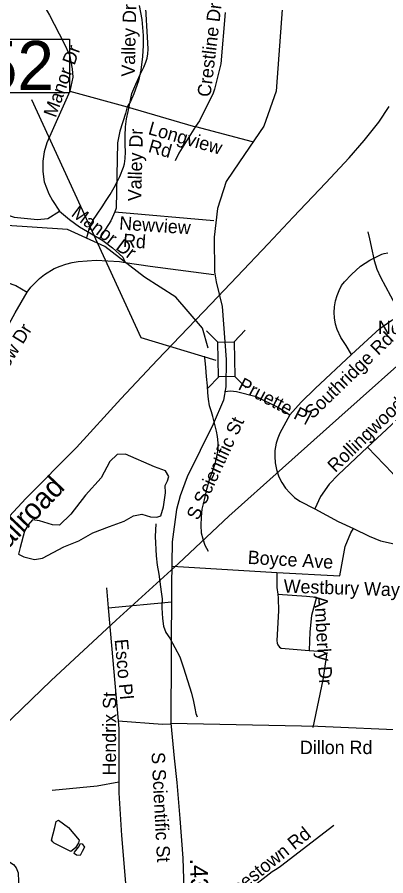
# Model space of a CAD drawing. Extents: x 1662474 to 1856135, y 779280 to 917889.
# Drawn here: x 1716545 to 1719166, y 808410 to 814512 of the extents above; entities that cross this region are included whole.
import ezdxf

# ---------------------------------------------------------------- set-up
doc = ezdxf.new("R2010")
doc.units = 0
for name, color, linetype in [('Exist Hydrographic Misc Water Feature', 7, 'Continuous'), ('Exist Hydrographic Pond Under 1500 Sq Ft', 7, 'Continuous'), ('Exist Railroad Mainline', 7, 'Continuous'), ('Exist Railroad Mainline Label', 7, 'Continuous'), ('Exist Road Non-System Type 51', 7, 'Continuous'), ('Exist Road Non-System Type 51 Label', 7, 'Continuous'), ('Exist Road Secondary Mileage Tenths English Label', 7, 'Continuous'), ('Exist Road Secondary Structure Standard Bridge CELL', 7, 'Continuous'), ('Exist Road Secondary Structure Standard Bridge Number Label', 7, 'Continuous'), ('Exist Road Secondary Type 51 Attributed', 7, 'Continuous'), ('Exist Road Secondary Type 51 Label', 7, 'Continuous'), ('Exist Utilities Electrical Transmission Line', 7, 'Continuous')]:
    doc.layers.add(name, color=color, linetype=linetype)

msp = doc.modelspace()

# ---------------------------------------------------------------- linework, layer by layer
at = {"layer": 'Exist Hydrographic Misc Water Feature'}
for points in [[(1717039.4, 812947.6), (1717062.1, 813021.5), (1717082.6, 813067.2), (1717112.9, 813113), (1717149.4, 813164.6), (1717177.9, 813208.4), (1717206.3, 813252.1), (1717234.8, 813301.9), (1717257.2, 813341.7), (1717275.5, 813379.5), (1717300.2, 813445.3), (1717308.4, 813469.2), (1717312.8, 813507.2), (1717315.2, 813555.2), (1717313.7, 813605.2), (1717312.3, 813669.3), (1717314.9, 813733.3), (1717323.4, 813789.2), (1717334, 813841.2), (1717361.2, 813968.9), (1717387.8, 814036.7), (1717422.5, 814110.3), (1717444.9, 814158.2), (1717459.3, 814192.1), (1717469.6, 814220), (1717473.8, 814251.9), (1717476.2, 814283.9), (1717474.7, 814330), (1717457.3, 814614.2)], [(1717903.3, 812159.8), (1717862.3, 812301.8), (1717673.3, 812522.3), (1717449.3, 812664.7), (1717167.4, 812883.8), (1716902.3, 813004.1), (1716435.3, 813033.3)], [(1719038.4, 812986.8), (1719049.8, 812936.6), (1719069.1, 812848.3), (1719082.4, 812784.2), (1719101.8, 812722), (1719127.3, 812663.7), (1719235.5, 812466.6)], [(1717904.5, 810714.7), (1717882.9, 810756.9), (1717867.3, 810803.1), (1717855.7, 810845.2), (1717852.3, 810901.3), (1717854.8, 810959.3), (1717861.4, 811015.2), (1717876, 811083.2), (1717892.7, 811159), (1717915.4, 811232.8), (1717935.9, 811290.6), (1717954.5, 811348.4), (1717967.1, 811402.4), (1717973.4, 811444.4), (1717973.9, 811488.3), (1717970.3, 811532.4), (1717962.6, 811570.5), (1717943.3, 811646.6), (1717935.7, 811674.8), (1717925.9, 811706.8), (1717912.3, 811751), (1717904.8, 811797.1), (1717901.2, 811843.1), (1717897.6, 811893.2), (1717892.3, 811959.2), (1717887, 812023.4), (1717881.3, 812073.4), (1717877.7, 812103.4)], [(1717530.3, 810912.3), (1717525.4, 810822.4), (1717534.2, 810684.2), (1717541.6, 810618.1), (1717553, 810554), (1717569.7, 810427.8), (1717575.3, 810379.7), (1717574.7, 810315.7), (1717578, 810239.7), (1717585.5, 810183.6), (1717602.9, 810139.4), (1717630.7, 810099.1), (1717701.4, 809966.4), (1717726.6, 809888.2), (1717755.8, 809797.8), (1717785, 809707.5), (1717798.4, 809649.4), (1717807.9, 809601.3), (1717815.5, 809563.2), (1717825.5, 809541.1)]]:
    msp.add_lwpolyline(points, dxfattribs=at)
at = {"layer": 'Exist Hydrographic Pond Under 1500 Sq Ft'}
for points in [[(1717520.4, 811317), (1717316, 811406.7), (1717257.2, 811403.7), (1717204.6, 811354.1), (1717142.6, 811239.6), (1717031.2, 811115.8), (1716925.9, 810979.7), (1716845.4, 810902.3), (1716795.8, 810905.4), (1716702.9, 810933.2), (1716653.4, 810939.4), (1716622.4, 810905.4), (1716597.7, 810859), (1716566.7, 810744.4), (1716554.3, 810694.9), (1716591.5, 810676.4), (1716668.9, 810657.8), (1716724.6, 810667.1), (1716876.3, 810747.5), (1716984.7, 810790.9), (1717083.8, 810846.6), (1717201.5, 810893), (1717306.7, 810930.1), (1717371.8, 810967.3), (1717430.6, 810979.7), (1717492.5, 810961.1), (1717539, 810958), (1717566.8, 810967.3), (1717585.4, 811032.3), (1717600.9, 811131.3), (1717597.8, 811183.9), (1717613.3, 811218), (1717622.6, 811248.9), (1717600.9, 811289.1), (1717520.4, 811317)], [(1716790.2, 808663.1), (1716813.6, 808753.9), (1716821.4, 808795.4), (1716839.6, 808805.8), (1716909.7, 808753.9), (1716985, 808663.1), (1716982.4, 808644.9), (1716959, 808608.6), (1716927.8, 808582.6), (1716860.3, 808616.3), (1716808.4, 808642.3), (1716798, 808652.7), (1716790.2, 808663.1)], [(1716953.8, 808577.4), (1716982.4, 808613.8), (1716995.3, 808639.7), (1717008.3, 808637.1), (1717023.9, 808613.8), (1717008.3, 808582.6), (1716992.8, 808554.1), (1716966.8, 808556.7), (1716951.2, 808569.6), (1716953.8, 808577.4)]]:
    msp.add_lwpolyline(points, dxfattribs=at)
at = {"layer": 'Exist Railroad Mainline'}
msp.add_lwpolyline([(1716372.3, 810841.3), (1716606, 811091.1), (1716966.3, 811453.1), (1717282.5, 811800), (1717543, 812077.8), (1717922.6, 812472), (1718109.2, 812670.3), (1718329.7, 812900.8), (1718506.7, 813091.4), (1718740.3, 813334.2), (1718905, 813513.7), (1719012.9, 813636), (1719115.8, 813767), (1719190.1, 813877.6)], dxfattribs=at)
at = {"layer": 'Exist Road Non-System Type 51'}
for p, q in [((1716918.9, 813987.1), (1717327.8, 813875.2)), ((1717813, 813735.9), (1718216.6, 813627.8)), ((1717238.5, 813128.4), (1717944.2, 813066.9)), ((1719483.6, 811875.9), (1719034.8, 811455.7)), ((1717649.2, 810611), (1718392.2, 810564.9)), ((1717180.8, 810455.7), (1717191, 810315.5)), ((1717191, 810315.5), (1717645, 810356.2)), ((1717191, 810315.5), (1717262.4, 809511.4))]:
    msp.add_line(p, q, dxfattribs=at)
for points in [[(1716708.4, 814641.7), (1716774.1, 814525.7), (1716877.6, 814330.9), (1716917, 814245.1), (1716936.9, 814146.4), (1716941.1, 814085.2), (1716918.9, 813987.1)], [(1717413.2, 814595.2), (1717430.6, 814495.5), (1717440.1, 814381.9), (1717441.1, 814310.9), (1717436.6, 814232.2), (1717424.1, 814135.1), (1717407, 814060.1), (1717375.2, 813968.7), (1717349.8, 813913.6), (1717327.8, 813875.2)], [(1718022.8, 814546.4), (1717993.1, 814180.2), (1717948.6, 814000.5), (1717939.2, 813971.6), (1717840.6, 813775.9), (1717813, 813735.9)], [(1716918.9, 813987.1), (1716756.6, 813619.9), (1716737.4, 813555.9), (1716727.5, 813490), (1716727.1, 813415.4), (1716738.2, 813342.5), (1716769.5, 813257.2), (1716796, 813208.6), (1716845.9, 813133)], [(1717327.8, 813875.2), (1717316.1, 813827.2), (1717276.2, 813702.4), (1717258.4, 813618.9), (1717248.1, 813154), (1717238.5, 813128.4)], [(1717327.8, 813875.2), (1717795.4, 813737.8), (1717813, 813735.9)], [(1717813, 813735.9), (1717695.6, 813545.4), (1717667.9, 813491.9)], [(1716387.4, 813244.9), (1716393.9, 813213.9), (1716402.5, 813190.5), (1716418, 813163.2), (1716434, 813143.8), (1716452.1, 813125.9), (1716472.9, 813111.5), (1716495.1, 813100.2), (1716525.1, 813090), (1716690.5, 813075.6), (1716762.1, 813081.9), (1716845.9, 813133)], [(1716845.9, 813133), (1716916.4, 813073.4), (1716989.4, 813022.2), (1717131.6, 812938.6)], [(1717238.5, 813128.4), (1717210.6, 813064.8), (1717131.6, 812938.6)], [(1717131.6, 812938.6), (1717153.4, 812926.2), (1717224.1, 812872.4), (1717295.6, 812806.5), (1717312.5, 812769.8)], [(1718920.9, 812114.9), (1718884.1, 812179.8), (1718846.1, 812235.2), (1718819.9, 812293.9), (1718809.1, 812330.9), (1718801.4, 812375.9), (1718799.4, 812413.9), (1718801.4, 812453), (1718808.9, 812497.4), (1718819, 812534.4), (1718833.8, 812570.1), (1718851.9, 812604.7), (1718871.2, 812632.5), (1718920.9, 812684.5), (1718985.4, 812742.5), (1719052.4, 812785.5), (1719138.6, 812829.1), (1719153.1, 812833.4), (1719181, 812838.6)], [(1716617.5, 812558.2), (1716642.4, 812592.6), (1716672.4, 812625.4), (1716704.9, 812656.2), (1716740.1, 812683.9), (1716808.9, 812725.2), (1716849.8, 812743.5), (1716891.8, 812758.2), (1716935.1, 812769), (1716979.1, 812776.1), (1717106.5, 812784.8), (1717273.4, 812775.9), (1717312.5, 812769.8)], [(1717312.5, 812769.8), (1717490.6, 812742.8), (1717943.4, 812683.4)], [(1716073.6, 812654.6), (1716473.4, 812626.5), (1716534.6, 812606), (1716617.5, 812558.2)], [(1716335.6, 812057.8), (1716530.1, 812411), (1716617.5, 812558.2)], [(1718920.9, 812114.9), (1719123.5, 812300.5), (1719209.9, 812358.2), (1719239.8, 812374)], [(1718483.6, 811686.1), (1718564.6, 811776.6), (1718662.6, 811874.2), (1718920.9, 812114.9)], [(1718020.1, 811853.2), (1718060.8, 811856.4), (1718105.4, 811853), (1718245.2, 811815.5), (1718403.2, 811739.1), (1718483.6, 811686.1)], [(1718483.6, 811686.1), (1718412.2, 811555.4), (1718397.2, 811520.2), (1718386.2, 811483.8), (1718377.9, 811433.6), (1718376, 811389.8), (1718379.9, 811345.2), (1718389.9, 811296.6), (1718406.6, 811246.8), (1718427.4, 811205.2), (1718452.6, 811166.2), (1718482.9, 811131), (1718516.9, 811099.5), (1718554.8, 811072.2), (1718660.8, 811017.1)], [(1719034.8, 811455.7), (1718826.9, 811259.1), (1718762.4, 811194.5), (1718702.8, 811106.4), (1718660.8, 811017.1)], [(1719034.8, 811455.7), (1719214.6, 811272.7), (1719283.9, 811218.7), (1719355, 811179.8), (1719422.9, 811159.4), (1719572, 811127.4), (1719660.2, 811102.1)], [(1718660.8, 811017.1), (1718828.2, 810927), (1718936.1, 810878.8)], [(1718392.2, 810564.9), (1718840, 810540.9), (1718840.2, 810543.1), (1718876.8, 810750.7), (1718918.2, 810846.8), (1718936.1, 810878.8)], [(1718936.1, 810878.8), (1719048.1, 810823.6), (1719128.5, 810790), (1719225.4, 810770.4), (1719330.1, 810760.9), (1719415.6, 810762.8), (1719546.4, 810777.2), (1719656, 810784.2)], [(1718392.2, 810564.9), (1718390.4, 810458.5), (1718397.2, 810412.1)], [(1718397.2, 810412.1), (1718401.4, 810384), (1718403.2, 810293.8), (1718390.1, 810081.4), (1718393.4, 810063), (1718398.6, 810050.9), (1718410.6, 810035.8), (1718421.1, 810028.4), (1718621.4, 810011.6)], [(1718397.2, 810412.1), (1718601.4, 810398.4), (1718673.1, 810390.9), (1718638.1, 810260.9), (1718625.4, 810143.4), (1718621.4, 810011.6)], [(1718621.4, 810011.6), (1718717.4, 810004.8), (1718735, 809995.4), (1718745.2, 809981.4), (1718718.5, 809802.9), (1718647.6, 809463.6)], [(1717262.4, 809511.4), (1717267.1, 809457.8), (1717268.6, 809078.5)], [(1717262.4, 809511.4), (1717578.4, 809487.2), (1717632.4, 809491.1)], [(1716793.6, 809017.9), (1717113.2, 809050.7), (1717268.6, 809078.5)], [(1717268.6, 809078.5), (1717268.4, 808999.8), (1717287.4, 808696.1), (1717323, 808272.2)], [(1717751.4, 807997.7), (1717766.4, 808000.5), (1717776.5, 808003.1), (1717790.6, 808009.2), (1717796, 808012.4), (1717840, 808040.4), (1718272, 808374.9), (1718359.1, 808440.4), (1718393.4, 808462.4), (1718418.1, 808478.2), (1718796.1, 808771.1)], [(1715949.2, 807481.2), (1716001.8, 808268), (1716019.6, 808348.4), (1716047.9, 808419.2), (1716081.6, 808477.5), (1716099.1, 808499.5), (1716114.9, 808513.7), (1716132.8, 808524.8), (1716165.5, 808536.8), (1716200.4, 808539.7), (1716458.6, 808517.9), (1716493.9, 808507.9), (1716519.4, 808490.6), (1716539, 808467), (1716553.4, 808431.2), (1716569.1, 808000.9), (1716599.9, 807495.9), (1716596.2, 807401.4)]]:
    msp.add_lwpolyline(points, dxfattribs=at)
at = {"layer": 'Exist Road Secondary Structure Standard Bridge CELL'}
for p, q in [((1717891.4, 812282.6), (1717972.7, 812203.8)), ((1718167.2, 812287.1), (1718088.5, 812205.7)), ((1717978.9, 811956), (1717900.2, 811874.7)), ((1718092, 811957.9), (1718173.4, 811879.2))]:
    msp.add_line(p, q, dxfattribs=at)
msp.add_lwpolyline([(1718088.5, 812205.7), (1718092.6, 811957.9), (1717976.8, 811956), (1717972.7, 812203.8)], close=True, dxfattribs=at)
at = {"layer": 'Exist Road Secondary Structure Standard Bridge Number Label'}
msp.add_lwpolyline([(1716273.6, 814356.2), (1716917.8, 814356.2), (1716917.8, 813973.9), (1716273.6, 813973.9)], close=True, dxfattribs=at)
msp.add_lwpolyline([(1717960.8, 812071.8), (1717427.7, 812233.8), (1716649.3, 813924.1)], dxfattribs=at)
at = {"layer": 'Exist Road Secondary Type 51 Attributed'}
for points in [[(1718639.8, 817717.2), (1718605.1, 817089), (1718512.1, 815749.9), (1718478.6, 815246.7), (1718385.7, 813986.9), (1718300, 813737.2), (1718124.9, 813483.7), (1718032, 813343.7), (1717968.7, 813153.6), (1717946.3, 812948.6), (1717948.4, 812701.9), (1717959.5, 812631.1), (1718002.5, 812455.7), (1718031.4, 812079.5)], [(1717637.6, 809495.9), (1718683.8, 809472.9), (1719333.9, 809445.6), (1719475.2, 809439), (1719534.6, 809440.5), (1719553.7, 809444.4), (1719593.4, 809458.7), (1719593.8, 809458.9), (1719619.7, 809475.1), (1719642.7, 809507.9), (1719675.6, 809583.4), (1719757.7, 809878.9), (1719921.9, 810476.3), (1719978.9, 810647.6), (1720010.6, 810737.7), (1720116.3, 810999.7), (1720247.7, 811307), (1720340.2, 811525.5), (1720565.3, 812056.5), (1720784, 812571.2)], [(1718031.4, 812079.5), (1718027.6, 811886), (1718012.6, 811790.7), (1717938, 811619.5), (1717753.8, 811246.2), (1717703.3, 811109.8), (1717677.8, 811014.1), (1717647.7, 810783.6), (1717641.4, 810474.4), (1717637.6, 809495.9)], [(1717637.6, 809495.9), (1717660.4, 809245.9), (1717679.8, 809073.1), (1717702.1, 808818), (1717723, 808536.2), (1717733.5, 808244), (1717757.8, 807969.1), (1717779, 807637.4), (1717798.2, 807433.1), (1717795.3, 807246.4)]]:
    msp.add_lwpolyline(points, dxfattribs=at)
at = {"layer": 'Exist Utilities Electrical Transmission Line'}
msp.add_lwpolyline([(1715330.2, 808405.6), (1715755.5, 808789.2), (1716106.2, 809133.9), (1716438.8, 809461.3), (1716787.4, 809798.2), (1717249.4, 810227.3), (1717691.2, 810629), (1718049.5, 810965.7), (1718432.3, 811308.1), (1718833.1, 811664), (1719416.5, 812185.8)], dxfattribs=at)

# ---------------------------------------------------------------- texts
at = {"layer": 'Exist Railroad Mainline Label'}
msp.add_text('Railroad', height=150, rotation=46.42288, dxfattribs=at).set_placement((1716377.7, 810622.1))
at = {"layer": 'Exist Road Non-System Type 51 Label'}
for s, rotation, p in [('Valley Dr', 88.71947, (1717380.8, 814088.7)), ('Crestline Dr', 83.09861, (1717919.3, 813941.8)), ('Manor Dr', 70.28058, (1716818.9, 813793.8)), ('Valley Dr', 88.71947, (1717427.5, 813203.5)), ('Longview', 344.04588, (1717470.8, 813682.2)), (' Rd', 344.04588, (1717437.3, 813564.9)), ('Manor Dr', 323.11426, (1716923.3, 813104.5)), ('Newview', 356.07395, (1717268.4, 813003.7)), (' Rd', 356.07395, (1717260.1, 812882)), ('Cedrow Dr', 58.46672, (1716337.9, 811779.9)), ('Southridge Rd', 44.06694, (1718645.3, 811652.2)), ('Pruette Pl', 332.28255, (1718109.5, 811871)), ('Rollingwood Rd', 44.08438, (1718806.6, 811270.9)), ('Boyce Ave', 356.66329, (1718182.7, 810627.5)), ('Westbury Way', 358.14448, (1718438.3, 810422.6)), ('Amberly Dr', 273.33741, (1718656.7, 810397.8)), ('Esco Pl', 275.23969, (1717238, 810088.9)), ('Hendrix St', 89.72739, (1717247.3, 809122.8)), ('Jamestown Rd', 38.63798, (1717986.1, 808166.8))]:
    msp.add_text(s, height=95, rotation=rotation, dxfattribs=at).set_placement(p)
msp.add_text('Northridge Dr', height=95, dxfattribs=at).set_placement((1719110.4, 812260.6))
at = {"layer": 'Exist Road Secondary Mileage Tenths English Label'}
msp.add_text('.43', height=125, rotation=272.04697, dxfattribs=at).set_placement((1717772.4, 808532.3))
at = {"layer": 'Exist Road Secondary Structure Standard Bridge Number Label'}
msp.add_text('52', height=350, dxfattribs=at).set_placement((1716286.2, 813993.7))
at = {"layer": 'Exist Road Secondary Type 51 Label'}
for rotation, p in [(65.13471, (1717831.6, 810930.8)), (272.95365, (1717499.7, 809286.7))]:
    msp.add_text('S Scientific St', height=95, rotation=rotation, dxfattribs=at).set_placement(p)
msp.add_text('Dillon Rd', height=95, dxfattribs=at).set_placement((1718555.3, 809275.3))

doc.saveas('drawing.dxf')
